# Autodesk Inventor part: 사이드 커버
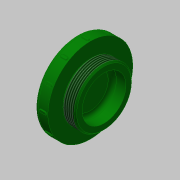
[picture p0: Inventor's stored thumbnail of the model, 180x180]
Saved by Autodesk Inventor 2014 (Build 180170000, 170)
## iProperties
Created: 2016-08
Part Number: 사이드 커버
Material: 스테인리스강
Document SubType Name: Modeling
Designer: mduedu
Density: 8.08 g/cm^3
Appearance: 진녹색
Author: mduedu
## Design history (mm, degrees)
sketch "스케치1"
  geometry: L1 (-5, 0)-(5, 0); L2 (-5, 0)-(-5, 31); L3 (-5, 31)-(5, 31); L4 (5, 31)-(5, 21); L5 (5, 21)-(15, 21); L6 (15, 21)-(15, 16); L7 (15, 16)-(5, 16); L8 (5, 16)-(5, 0); 2 further points
  constraints: 16 end point, 4 parallel, 2 perpendicular, 1 coincident, 1 collinear, 1 horizontal, 1 midpoint, 1 vertical
  dimensions: "d0" = 10 distance of L1.start L1.end; "d2" = 62 diameter of L3 L1; "d3" = 42 diameter of L5 L1; "d4" = 10 distance between parallel lines of L6 L8; "d5" = 5 distance of L5.end L6.end
revolve "회전1" sketch "스케치1" stored, may be unused: angle "d6" = 90 deg
fillet "모깎기1" dims "d7" = 3
sketch "스케치2"
  geometry: L1 (5, -31)-(5, 31) reference; L2 (5, 21)-(15, 21) reference; L3 (0, 0)-(5, 0); L4 (5, 21)-(6, 21); L5 (6, 21)-(6, 20); L6 (6, 20)-(5, 20); L7 (5, 20)-(5, 21)
  constraints: 10 end point, 2 parallel, 1 horizontal, 1 midpoint, 1 perpendicular
  dimensions: "d8" = 1 distance of L2.start L4.end; "d9" = 40 diameter of L6 L3
revolve "회전2" sketch "스케치2" stored, may be unused: angle "d10" = 90 deg
fillet "모깎기2" dims "d11" = 3
feature "스레드1" dims "d12" = 10, "d13" = 0
chamfer "모따기1" distance "d14" = 1; stored, may be unused: second distance "d15" = 2, angle "d16" = 45 deg
node "작업 평면1"
sketch "스케치3"
  geometry: L1 (1, -1)-(-4, -1); L2 (-4, -1)-(-4, 1); L3 (-4, 1)-(1, 1); L4 (1, 1)-(1, -1); 2 further points
  constraints: 8 end point, 2 parallel, 1 horizontal, 1 horizontal alignment, 1 midpoint, 1 perpendicular
  dimensions: "d18" = 2 distance of L3.end L1.start; "d20" = 5 distance of L1.start L1.end; "d21" = 1 distance from line of L4 point (0, 0)
extrude "돌출1" join sketch "스케치3" stored distance "d22" = 10; taper "d23" = 0 deg
fillet "모깎기3" dims "d24" = 1
fillet "모깎기4" dims "d25" = 0.2
sketch "스케치4"
  geometry: 2 further points
  constraints: 1 coincident, 1 other
feature "엠보싱1" sketch "스케치4" dims "d0" = 10, "d2" = 62, "d3" = 42, "d4" = 10, "d5" = 5, "d29" = 0.5, "d30" = 0
node "솔리드1"
pattern_circular "원형 패턴1" dims "d27" = 360 deg
other parameters: "d17" = 31.5
